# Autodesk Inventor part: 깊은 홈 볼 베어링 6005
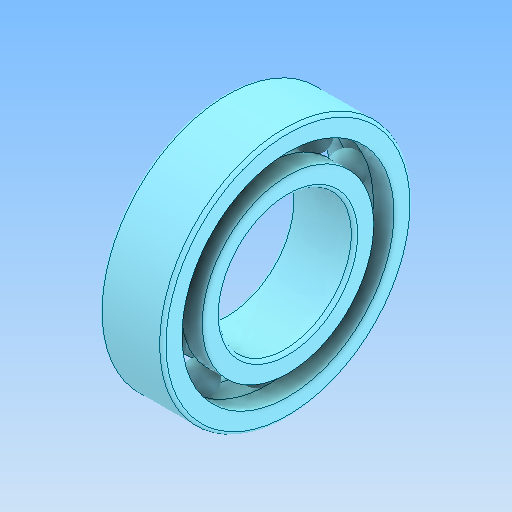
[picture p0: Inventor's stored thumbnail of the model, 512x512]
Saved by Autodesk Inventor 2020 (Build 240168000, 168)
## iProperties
Created: 2025-11
Part Number: 깊은 홈 볼 베어링 6005
Material: 강철, 연강
Description: 깊은 그루브 볼 베어링
Document SubType Name: Modeling
Designer: PC2-06
Density: 7.85 g/cm^3
Appearance: 기본값
Author: jhkim
Sending System: Autodesk Inventor 2026
Preprocessor: ST-DEVELOPER v20.1
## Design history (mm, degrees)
feature "Solid1"
feature "Solid1:1"
feature "Solid1:2"
feature "Solid1:3"
feature "Solid1:4"
feature "Solid1:5"
feature "Solid1:6"
feature "Solid1:7"
feature "Solid1:8"
feature "Solid1:9"
feature "Solid1:10"
feature "Solid1:11"
node "솔리드1"
node "솔리드2"
node "솔리드3"
node "솔리드4"
node "솔리드5"
node "솔리드6"
node "솔리드7"
node "솔리드8"
node "솔리드9"
node "솔리드10"
node "솔리드11"
node "솔리드12"
